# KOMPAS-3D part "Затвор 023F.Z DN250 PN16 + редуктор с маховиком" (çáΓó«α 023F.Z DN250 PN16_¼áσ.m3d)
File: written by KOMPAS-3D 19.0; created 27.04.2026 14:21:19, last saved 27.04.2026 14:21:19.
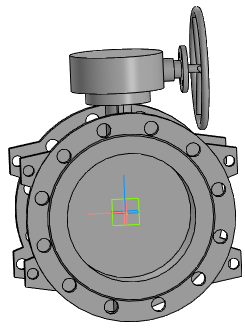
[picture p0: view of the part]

Document properties: Полное имя файла: ..\..\Затвор 023F.Z DN200-DN1600_с маховиком\Затвор 023F.Z DN250 PN16 + редуктор с маховиком.a3d

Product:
- Part/product: Затвор 023F.Z DN250 PN16 + редуктор с маховиком
    Масса: 75.9712

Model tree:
1. Операция без истории:1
